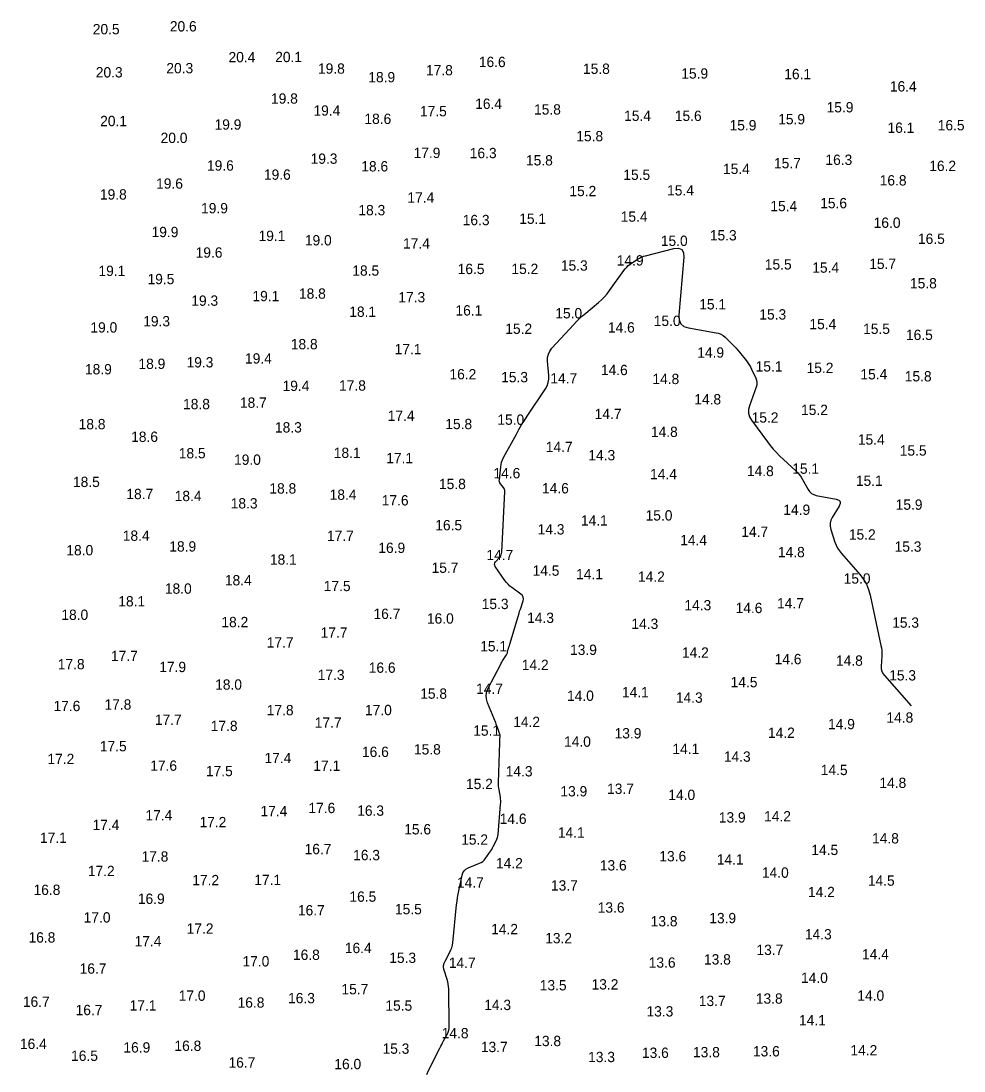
# Model space of a CAD drawing. Extents: x 1023796 to 1112670, y 656573 to 837340.
# Drawn here: x 1110028 to 1110485, y 672721 to 673230 of the extents above; entities that cross this region are included whole.
import ezdxf

# ---------------------------------------------------------------- set-up
doc = ezdxf.new("R2010")
doc.units = 0
doc.layers.add('V-CHAN-CONT-15FT', color=7, linetype='Continuous')
doc.layers.add('V-TOPO-SOUN', color=7, linetype='Continuous')

msp = doc.modelspace()

# ---------------------------------------------------------------- linework, layer by layer
at = {"layer": 'V-CHAN-CONT-15FT'}
msp.add_lwpolyline([(1110224.62, 672719.26), (1110225.38, 672721.12), (1110230.9, 672732.05), (1110231.34, 672732.92), (1110231.79, 672733.78), (1110232.24, 672734.63), (1110232.69, 672735.49), (1110234.53, 672738.9), (1110234.93, 672739.77), (1110235.21, 672740.66), (1110235.38, 672741.59), (1110235.42, 672742.54), (1110235.2, 672760.75), (1110235.14, 672761.92), (1110235, 672763.08), (1110234.76, 672764.23), (1110234.44, 672765.36), (1110232.99, 672769.85), (1110232.74, 672770.97), (1110232.73, 672772.06), (1110232.95, 672773.13), (1110233.39, 672774.17), (1110235.75, 672778.5), (1110236.28, 672779.59), (1110236.69, 672780.71), (1110236.98, 672781.87), (1110237.16, 672783.06), (1110239.04, 672801.54), (1110239.23, 672803.25), (1110239.47, 672804.95), (1110239.75, 672806.64), (1110240.08, 672808.32), (1110241.64, 672815.84), (1110242.03, 672817.02), (1110242.65, 672818), (1110243.51, 672818.79), (1110244.6, 672819.37), (1110250.18, 672821.61), (1110250.99, 672822), (1110251.72, 672822.5), (1110252.37, 672823.1), (1110252.93, 672823.8), (1110255.17, 672827.03), (1110255.61, 672827.69), (1110256.03, 672828.36), (1110256.42, 672829.05), (1110256.8, 672829.74), (1110258.24, 672832.57), (1110258.57, 672833.29), (1110258.82, 672834.03), (1110259, 672834.78), (1110259.1, 672835.56), (1110260.37, 672850.18), (1110260.42, 672851.06), (1110260.41, 672851.94), (1110260.34, 672852.81), (1110260.22, 672853.69), (1110259.62, 672857.18), (1110259.49, 672858.05), (1110259.4, 672858.93), (1110259.36, 672859.81), (1110259.37, 672860.69), (1110259.93, 672880.23), (1110259.95, 672880.6), (1110259.96, 672880.96), (1110259.98, 672881.33), (1110260, 672881.7), (1110260.09, 672883.16), (1110260.09, 672883.53), (1110260.06, 672883.89), (1110259.99, 672884.24), (1110259.88, 672884.59), (1110258.85, 672887.35), (1110258.63, 672887.93), (1110258.41, 672888.5), (1110258.19, 672889.08), (1110257.96, 672889.65), (1110254.02, 672899.44), (1110253.49, 672901.26), (1110253.37, 672903.05), (1110253.66, 672904.82), (1110254.37, 672906.57), (1110260.38, 672918.07), (1110260.67, 672918.61), (1110260.98, 672919.15), (1110261.29, 672919.67), (1110261.61, 672920.19), (1110263.22, 672922.71), (1110263.4, 672923.01), (1110263.55, 672923.32), (1110263.66, 672923.64), (1110263.75, 672923.98), (1110264.06, 672925.34), (1110264.14, 672925.68), (1110264.23, 672926.02), (1110264.32, 672926.36), (1110264.42, 672926.69), (1110268.65, 672940.76), (1110268.96, 672941.78), (1110269.27, 672942.79), (1110269.59, 672943.81), (1110269.92, 672944.82), (1110271.24, 672948.85), (1110271.42, 672949.81), (1110271.3, 672950.67), (1110270.89, 672951.44), (1110270.17, 672952.11), (1110265.83, 672955.22), (1110264.86, 672955.99), (1110263.96, 672956.83), (1110263.14, 672957.74), (1110262.4, 672958.73), (1110257.78, 672965.51), (1110257.49, 672966.09), (1110257.42, 672966.66), (1110257.57, 672967.22), (1110257.94, 672967.76), (1110259.86, 672969.89), (1110260.29, 672970.44), (1110260.6, 672971.04), (1110260.8, 672971.69), (1110260.9, 672972.38), (1110262.44, 673001.76), (1110262.42, 673002.32), (1110262.3, 673002.84), (1110262.09, 673003.33), (1110261.78, 673003.79), (1110260.34, 673005.57), (1110260.03, 673006.03), (1110259.83, 673006.53), (1110259.73, 673007.05), (1110259.74, 673007.6), (1110260.38, 673013.73), (1110260.57, 673014.92), (1110260.86, 673016.08), (1110261.28, 673017.2), (1110261.8, 673018.29), (1110267.99, 673029.64), (1110269.24, 673031.88), (1110270.54, 673034.08), (1110271.89, 673036.25), (1110273.28, 673038.4), (1110282.04, 673051.51), (1110282.88, 673053.02), (1110283.44, 673054.61), (1110283.72, 673056.26), (1110283.71, 673057.99), (1110283.12, 673065.06), (1110283.14, 673066.77), (1110283.5, 673068.36), (1110284.19, 673069.84), (1110285.22, 673071.21), (1110295.82, 673082.76), (1110297.2, 673084.22), (1110298.62, 673085.62), (1110300.09, 673086.98), (1110301.61, 673088.29), (1110307.78, 673093.42), (1110309.27, 673094.75), (1110310.67, 673096.16), (1110311.98, 673097.67), (1110313.19, 673099.26), (1110320.09, 673108.96), (1110320.75, 673109.81), (1110321.48, 673110.59), (1110322.27, 673111.3), (1110323.13, 673111.94), (1110326.71, 673114.38), (1110327.62, 673114.94), (1110328.57, 673115.42), (1110329.57, 673115.81), (1110330.6, 673116.11), (1110344.39, 673119.53), (1110346.68, 673119.76), (1110348.25, 673119.15), (1110349.09, 673117.7), (1110349.21, 673115.4), (1110346.73, 673087.35), (1110346.85, 673084.97), (1110347.69, 673083.13), (1110349.25, 673081.85), (1110351.52, 673081.11), (1110364.81, 673078.8), (1110366.02, 673078.5), (1110367.15, 673078.03), (1110368.2, 673077.4), (1110369.16, 673076.6), (1110372.84, 673073.06), (1110373.74, 673072.17), (1110374.61, 673071.24), (1110375.45, 673070.29), (1110376.26, 673069.3), (1110379.5, 673065.2), (1110380.22, 673064.24), (1110380.88, 673063.25), (1110381.48, 673062.22), (1110382.03, 673061.15), (1110384.1, 673056.81), (1110384.5, 673055.72), (1110384.66, 673054.62), (1110384.6, 673053.51), (1110384.3, 673052.39), (1110380.99, 673043.36), (1110380.54, 673041.51), (1110380.55, 673039.73), (1110381.04, 673038.02), (1110381.99, 673036.37), (1110389.73, 673025.83), (1110391.09, 673024.06), (1110392.54, 673022.36), (1110394.06, 673020.73), (1110395.65, 673019.17), (1110403.48, 673011.88), (1110404.43, 673010.91), (1110405.3, 673009.88), (1110406.09, 673008.78), (1110406.79, 673007.62), (1110409.43, 673002.83), (1110410.17, 673001.75), (1110411.09, 673000.91), (1110412.17, 673000.3), (1110413.43, 672999.93), (1110423.01, 672998.12), (1110424.29, 672997.68), (1110424.97, 672996.98), (1110425.04, 672996), (1110424.5, 672994.76), (1110421.16, 672989.25), (1110420.49, 672987.85), (1110420.16, 672986.41), (1110420.15, 672984.94), (1110420.49, 672983.42), (1110422.48, 672977.29), (1110423.05, 672975.79), (1110423.76, 672974.38), (1110424.61, 672973.04), (1110425.59, 672971.79), (1110434.64, 672961.42), (1110436.34, 672959.2), (1110437.73, 672956.83), (1110438.8, 672954.3), (1110439.55, 672951.61), (1110444.78, 672927.23), (1110445.01, 672925.97), (1110445.15, 672924.71), (1110445.2, 672923.44), (1110445.17, 672922.16), (1110444.88, 672917.05), (1110444.93, 672915.81), (1110445.2, 672914.65), (1110445.7, 672913.58), (1110446.44, 672912.58), (1110459.41, 672897.95)], dxfattribs=at)

# ---------------------------------------------------------------- texts
at = {"layer": 'V-TOPO-SOUN'}
for s, p in [('20.5 ', (1110062.61, 673223.41)), ('20.6 ', (1110099.98, 673224.79)), ('20.4 ', (1110128.43, 673209.86)), ('20.1 ', (1110151.05, 673209.93)), ('16.6 ', (1110249.79, 673207.53)), ('20.3 ', (1110064.07, 673202.5)), ('20.3 ', (1110098.28, 673204.51)), ('19.8 ', (1110171.8, 673204.32)), ('17.8 ', (1110224.17, 673203.53)), ('15.8 ', (1110300.3, 673204.23)), ('15.9 ', (1110347.95, 673201.93)), ('16.1 ', (1110397.89, 673201.66)), ('18.9 ', (1110196.21, 673200.14)), ('16.4 ', (1110449.09, 673195.69)), ('19.8 ', (1110149.03, 673189.8)), ('16.4 ', (1110248.01, 673187.25)), ('19.4 ', (1110169.62, 673183.98)), ('17.5 ', (1110221.23, 673183.65)), ('15.8 ', (1110276.56, 673184.51)), ('15.4 ', (1110320.24, 673181.44)), ('15.6 ', (1110344.82, 673181.41)), ('15.9 ', (1110418.42, 673185.57)), ('20.1 ', (1110066.19, 673178.89)), ('19.9 ', (1110121.65, 673177.2)), ('18.6 ', (1110194.32, 673179.96)), ('15.9 ', (1110371.37, 673176.84)), ('15.9 ', (1110394.95, 673179.78)), ('16.1 ', (1110447.94, 673175.65)), ('16.5 ', (1110472.31, 673176.86)), ('20.0 ', (1110095.5, 673170.72)), ('15.8 ', (1110297.04, 673171.56)), ('19.3 ', (1110168.23, 673160.65)), ('17.9 ', (1110218.15, 673163.45)), ('16.3 ', (1110245.4, 673163.37)), ('19.6 ', (1110117.97, 673157.33)), ('18.6 ', (1110192.8, 673156.94)), ('15.8 ', (1110272.66, 673159.84)), ('15.4 ', (1110368.18, 673155.7)), ('15.7 ', (1110392.9, 673158.46)), ('16.3 ', (1110417.85, 673160.11)), ('16.2 ', (1110468.18, 673157.15)), ('19.6 ', (1110145.58, 673152.91)), ('15.5 ', (1110319.85, 673152.84)), ('16.8 ', (1110444.16, 673150.14)), ('19.6 ', (1110093.32, 673148.58)), ('15.4 ', (1110341.08, 673145.29)), ('19.8 ', (1110066.07, 673143.32)), ('17.4 ', (1110215.18, 673141.82)), ('15.2 ', (1110293.7, 673144.95)), ('19.9 ', (1110115.12, 673136.65)), ('18.3 ', (1110191.39, 673135.7)), ('15.4 ', (1110391.15, 673137.68)), ('15.6 ', (1110415.31, 673139.09)), ('16.3 ', (1110241.99, 673130.9)), ('15.1 ', (1110269.38, 673131.54)), ('15.4 ', (1110318.58, 673132.56)), ('19.9 ', (1110091.11, 673125.1)), ('16.0 ', (1110441.24, 673129.61)), ('19.1 ', (1110142.98, 673123.25)), ('19.0 ', (1110165.44, 673121.09)), ('15.0 ', (1110338.03, 673120.84)), ('15.3 ', (1110361.8, 673123.5)), ('16.5 ', (1110462.71, 673121.82)), ('19.6 ', (1110112.47, 673115.15)), ('17.4 ', (1110213.07, 673119.57)), ('14.9 ', (1110316.65, 673111.35)), ('15.7 ', (1110439.08, 673109.65)), ('19.1 ', (1110065.36, 673106.28)), ('18.5 ', (1110188.46, 673106.41)), ('16.5 ', (1110239.54, 673107.19)), ('15.2 ', (1110265.6, 673107.23)), ('15.3 ', (1110289.58, 673108.85)), ('15.5 ', (1110388.45, 673109.41)), ('15.4 ', (1110411.47, 673107.85)), ('19.5 ', (1110089.15, 673102.3)), ('15.8 ', (1110458.84, 673100.26)), ('18.8 ', (1110162.58, 673095.25)), ('19.3 ', (1110110.38, 673091.83)), ('19.1 ', (1110140.04, 673094.05)), ('17.3 ', (1110210.77, 673093.5)), ('15.1 ', (1110356.66, 673090.05)), ('18.1 ', (1110186.96, 673086.47)), ('16.1 ', (1110238.46, 673087.11)), ('15.0 ', (1110286.87, 673085.72)), ('15.3 ', (1110385.8, 673085.16)), ('19.0 ', (1110061.47, 673078.85)), ('19.3 ', (1110087.05, 673081.85)), ('15.0 ', (1110334.6, 673082.03)), ('15.4 ', (1110410.09, 673080.46)), ('15.2 ', (1110262.62, 673078.21)), ('14.6 ', (1110312.38, 673078.84)), ('15.5 ', (1110436.12, 673078.17)), ('16.5 ', (1110456.89, 673075.25)), ('18.8 ', (1110158.63, 673070.74)), ('19.4 ', (1110136.43, 673063.82)), ('17.1 ', (1110208.97, 673068.34)), ('14.9 ', (1110355.69, 673066.68)), ('18.9 ', (1110058.83, 673058.58)), ('18.9 ', (1110084.76, 673061.21)), ('19.3 ', (1110108.07, 673061.94)), ('15.1 ', (1110384.01, 673059.96)), ('15.2 ', (1110408.71, 673059.26)), ('16.2 ', (1110235.55, 673056.17)), ('15.3 ', (1110260.62, 673054.75)), ('14.7 ', (1110284.48, 673054.17)), ('14.6 ', (1110308.98, 673058.21)), ('14.8 ', (1110333.95, 673053.87)), ('15.4 ', (1110434.81, 673056.14)), ('15.8 ', (1110456.32, 673055.17)), ('19.4 ', (1110154.62, 673050.53)), ('17.8 ', (1110182.02, 673050.71)), ('14.8 ', (1110354.25, 673044.01)), ('18.8 ', (1110106.39, 673041.7)), ('18.7 ', (1110133.96, 673042.39)), ('15.2 ', (1110406.03, 673038.88)), ('17.4 ', (1110205.64, 673036.06)), ('15.0 ', (1110258.78, 673034.14)), ('14.7 ', (1110305.97, 673036.91)), ('15.2 ', (1110382.06, 673035.19)), ('18.8 ', (1110055.76, 673031.98)), ('18.3 ', (1110150.95, 673030.41)), ('15.8 ', (1110233.53, 673032.03)), ('14.8 ', (1110333.23, 673028.25)), ('18.6 ', (1110081.22, 673025.85)), ('15.4 ', (1110433.58, 673024.51)), ('18.5 ', (1110104.31, 673017.88)), ('18.1 ', (1110179.46, 673018.07)), ('14.7 ', (1110282.24, 673020.91)), ('15.5 ', (1110453.89, 673019.2)), ('19.0 ', (1110131.11, 673014.75)), ('17.1 ', (1110204.9, 673015.51)), ('14.3 ', (1110302.89, 673016.92)), ('14.6 ', (1110256.88, 673008.21)), ('14.4 ', (1110332.83, 673007.75)), ('14.8 ', (1110379.78, 673009.26)), ('15.1 ', (1110401.76, 673010.39)), ('18.5 ', (1110053.01, 673003.97)), ('15.8 ', (1110230.47, 673002.97)), ('15.1 ', (1110432.62, 673004.54)), ('18.7 ', (1110078.89, 672998.11)), ('18.8 ', (1110148.24, 673000.82)), ('18.4 ', (1110177.47, 672997.78)), ('14.6 ', (1110280.41, 673000.88)), ('18.4 ', (1110102.34, 672997.15)), ('18.3 ', (1110129.49, 672993.58)), ('17.6 ', (1110202.72, 672995.04)), ('15.9 ', (1110451.9, 672992.96)), ('15.0 ', (1110330.65, 672987.74)), ('14.9 ', (1110397.44, 672990.49)), ('16.5 ', (1110228.67, 672983.01)), ('14.1 ', (1110299.3, 672985.28)), ('18.4 ', (1110077.16, 672977.91)), ('17.7 ', (1110176.15, 672977.81)), ('14.3 ', (1110278.3, 672980.98)), ('14.7 ', (1110377.06, 672979.84)), ('15.2 ', (1110429.21, 672978.49)), ('18.9 ', (1110099.72, 672972.7)), ('16.9 ', (1110201.07, 672972.03)), ('14.4 ', (1110347.43, 672975.78)), ('15.3 ', (1110451.39, 672972.62)), ('18.0 ', (1110049.8, 672970.86)), ('14.7 ', (1110253.5, 672968.54)), ('14.8 ', (1110394.82, 672969.95)), ('18.1 ', (1110148.49, 672966.35)), ('15.7 ', (1110226.88, 672962.39)), ('14.5 ', (1110275.85, 672960.97)), ('14.1 ', (1110296.94, 672959.27)), ('14.2 ', (1110326.96, 672958.05)), ('15.0 ', (1110426.7, 672957.15)), ('18.0 ', (1110097.56, 672952.25)), ('18.4 ', (1110126.66, 672956.3)), ('17.5 ', (1110174.61, 672953.51)), ('18.1 ', (1110074.98, 672946.11)), ('15.3 ', (1110251.19, 672944.81)), ('14.3 ', (1110349.47, 672944.23)), ('14.6 ', (1110374.28, 672942.86)), ('14.7 ', (1110394.38, 672945.13)), ('18.0 ', (1110047.38, 672939.57)), ('16.7 ', (1110198.72, 672940.03)), ('16.0 ', (1110224.62, 672937.77)), ('14.3 ', (1110273.22, 672938.1)), ('18.2 ', (1110124.97, 672936.04)), ('14.3 ', (1110323.78, 672935.2)), ('15.3 ', (1110450.21, 672935.78)), ('17.7 ', (1110173.1, 672930.94)), ('17.7 ', (1110146.97, 672926.17)), ('15.1 ', (1110250.46, 672924.3)), ('13.9 ', (1110294.02, 672922.61)), ('14.2 ', (1110348.28, 672921.25)), ('17.7 ', (1110071.43, 672919.62)), ('14.6 ', (1110393.21, 672918.09)), ('14.8 ', (1110422.96, 672917.35)), ('17.8 ', (1110045.64, 672915.63)), ('17.9 ', (1110094.83, 672914.28)), ('16.6 ', (1110196.42, 672913.94)), ('14.2 ', (1110270.63, 672915.27)), ('17.3 ', (1110171.69, 672910.46)), ('14.5 ', (1110371.88, 672906.92)), ('15.3 ', (1110448.76, 672910.21)), ('18.0 ', (1110121.94, 672905.76)), ('15.8 ', (1110221.38, 672901.35)), ('14.7 ', (1110248.48, 672903.74)), ('14.1 ', (1110319.18, 672902.05)), ('17.8 ', (1110068.29, 672896.09)), ('14.0 ', (1110292.56, 672900.32)), ('14.3 ', (1110345.33, 672899.41)), ('17.6 ', (1110043.57, 672895.35)), ('17.8 ', (1110146.97, 672893.35)), ('17.0 ', (1110194.6, 672893.39)), ('17.7 ', (1110092.71, 672888.69)), ('17.8 ', (1110119.81, 672885.7)), ('17.7 ', (1110170.24, 672887.3)), ('14.2 ', (1110266.45, 672887.63)), ('14.9 ', (1110419.11, 672886.58)), ('14.8 ', (1110447.41, 672889.77)), ('15.1 ', (1110247.08, 672883.43)), ('13.9 ', (1110315.61, 672882.12)), ('14.2 ', (1110389.98, 672882.39)), ('17.5 ', (1110066.03, 672875.88)), ('14.0 ', (1110291.11, 672878.09)), ('16.6 ', (1110193.14, 672873.14)), ('15.8 ', (1110218.34, 672874.34)), ('14.1 ', (1110343.64, 672874.55)), ('14.3 ', (1110368.59, 672870.83)), ('17.2 ', (1110040.63, 672869.69)), ('17.6 ', (1110090.46, 672866.43)), ('17.4 ', (1110145.87, 672870.14)), ('17.1 ', (1110169.55, 672866.41)), ('17.5 ', (1110117.46, 672863.83)), ('14.3 ', (1110262.82, 672863.7)), ('14.5 ', (1110415.59, 672864.35)), ('15.2 ', (1110243.58, 672857.56)), ('13.7 ', (1110311.97, 672855.24)), ('14.8 ', (1110444.02, 672858.12)), ('13.9 ', (1110289.34, 672854.02)), ('14.0 ', (1110341.67, 672852.28)), ('17.6 ', (1110167.17, 672845.93)), ('17.4 ', (1110088.16, 672842.37)), ('17.4 ', (1110143.93, 672844.44)), ('16.3 ', (1110190.81, 672844.64)), ('14.6 ', (1110259.91, 672840.71)), ('13.9 ', (1110366.15, 672841.37)), ('14.2 ', (1110388.11, 672841.89)), ('17.4 ', (1110062.48, 672837.69)), ('17.2 ', (1110114.36, 672839.07)), ('15.6 ', (1110213.62, 672835.6)), ('17.1 ', (1110037, 672831.49)), ('15.2 ', (1110241.24, 672830.62)), ('14.1 ', (1110288.12, 672834.03)), ('14.8 ', (1110440.46, 672831.21)), ('16.7 ', (1110165.31, 672826.02)), ('14.5 ', (1110411.02, 672825.6)), ('17.8 ', (1110086.25, 672822.41)), ('16.3 ', (1110188.85, 672823.1)), ('13.6 ', (1110337.32, 672822.53)), ('14.1 ', (1110365.19, 672821.01)), ('17.2 ', (1110060.21, 672815.38)), ('14.2 ', (1110258.11, 672819.18)), ('13.6 ', (1110308.46, 672818.12)), ('14.0 ', (1110387.04, 672814.59)), ('17.2 ', (1110110.84, 672810.96)), ('17.1 ', (1110140.92, 672811.06)), ('14.7 ', (1110239.2, 672809.8)), ('14.5 ', (1110438.41, 672810.72)), ('16.8 ', (1110033.89, 672806.26)), ('13.7 ', (1110284.77, 672808.37)), ('14.2 ', (1110409.39, 672805.19)), ('16.9 ', (1110084.47, 672801.93)), ('16.5 ', (1110187.05, 672802.96)), ('16.7 ', (1110162.07, 672796.34)), ('15.5 ', (1110209.13, 672796.89)), ('13.6 ', (1110307.43, 672797.68)), ('17.0 ', (1110058.2, 672792.89)), ('13.8 ', (1110333.12, 672791.03)), ('13.9 ', (1110361.53, 672792.56)), ('17.2 ', (1110108.13, 672787.47)), ('14.2 ', (1110255.77, 672787.23)), ('14.3 ', (1110407.89, 672784.7)), ('16.8 ', (1110031.45, 672783.19)), ('17.4 ', (1110082.86, 672781.34)), ('13.2 ', (1110281.96, 672782.83)), ('16.8 ', (1110159.68, 672774.77)), ('16.4 ', (1110184.82, 672778.07)), ('13.7 ', (1110384.41, 672777.16)), ('14.4 ', (1110435.59, 672775.01)), ('17.0 ', (1110135.2, 672771.61)), ('15.3 ', (1110206.36, 672773.31)), ('14.7 ', (1110235.25, 672770.89)), ('13.6 ', (1110332.17, 672771)), ('13.8 ', (1110358.97, 672772.54)), ('16.7 ', (1110056.23, 672768.09)), ('14.0 ', (1110406.02, 672763.61)), ('13.5 ', (1110279.34, 672760)), ('13.2 ', (1110304.44, 672760.43)), ('17.0 ', (1110104.27, 672754.96)), ('16.3 ', (1110157.29, 672753.76)), ('15.7 ', (1110183.19, 672758.1)), ('13.8 ', (1110384.1, 672753.55)), ('14.0 ', (1110433.32, 672755)), ('16.7 ', (1110028.72, 672752.03)), ('17.1 ', (1110080.48, 672750.24)), ('16.8 ', (1110132.82, 672751.63)), ('15.5 ', (1110204.48, 672750.14)), ('14.3 ', (1110252.4, 672750.46)), ('13.7 ', (1110356.45, 672752.41)), ('16.7 ', (1110054.28, 672747.99)), ('13.3 ', (1110331.09, 672747.35)), ('14.1 ', (1110405.03, 672743.06)), ('14.8 ', (1110231.79, 672736.79)), ('13.8 ', (1110276.66, 672732.98)), ('16.4 ', (1110027.29, 672731.58)), ('16.9 ', (1110077.47, 672729.88)), ('16.8 ', (1110102.2, 672730.65)), ('15.3 ', (1110203.1, 672729.27)), ('13.7 ', (1110250.78, 672730.08)), ('13.6 ', (1110382.69, 672727.99)), ('14.2 ', (1110429.98, 672728.5)), ('16.5 ', (1110052.1, 672725.83)), ('13.3 ', (1110302.79, 672725.22)), ('13.6 ', (1110328.88, 672727.28)), ('13.8 ', (1110353.65, 672727.58)), ('16.7 ', (1110128.42, 672722.54)), ('16.0 ', (1110179.74, 672721.79))]:
    msp.add_text(s, height=5, dxfattribs=at).set_placement(p)

doc.saveas('drawing.dxf')
